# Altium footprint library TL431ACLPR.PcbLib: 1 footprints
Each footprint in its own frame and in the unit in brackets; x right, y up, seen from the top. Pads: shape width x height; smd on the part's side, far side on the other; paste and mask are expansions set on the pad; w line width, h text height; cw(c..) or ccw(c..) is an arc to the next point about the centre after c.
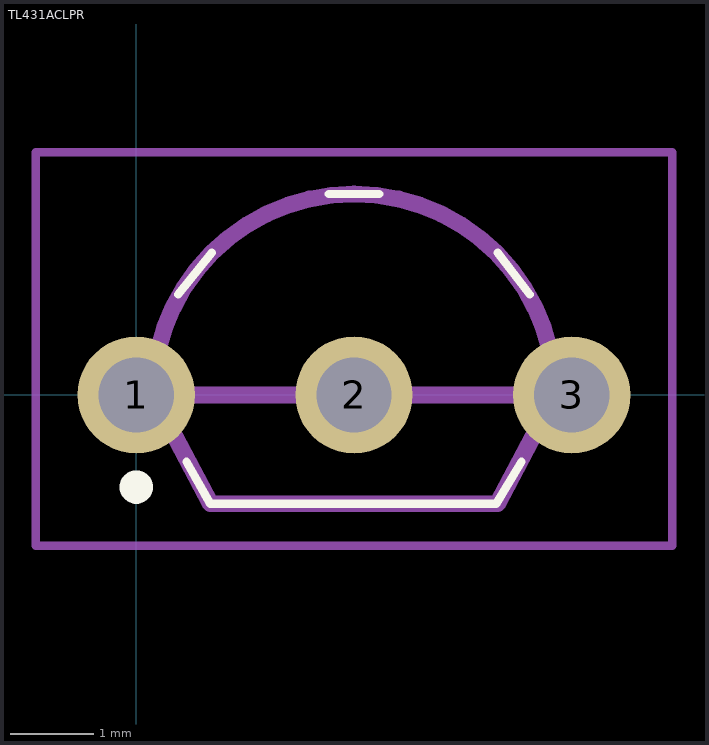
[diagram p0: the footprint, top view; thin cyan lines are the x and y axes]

## TL431ACLPR [mm]
pads (3):
  round 1.4 hole 0.9: 1(0,0) 2(2.6,0) 3(5.2,0)
Top Overlay:
  lines w0.1: 0.5,1.2 0.9,1.7 ; 0.6,-0.8 0.885,-1.3 4.3,-1.3 4.6,-0.8 ; 2.3,2.4 2.9,2.4 ; 4.315,1.7 4.7,1.2
  lines w0.2: -0.1,-1.1 -0.1,-1.1 ; -0.1,-1.1 ccw(c0,-1.1) 0.1,-1.1 ; -0.1,-1.1 cw(c0,-1.1) 0.1,-1.1 ; 0.1,-1.1 0.1,-1.1
Mechanical 15:
  lines w0.2: 0.2,0 5,0 ; 0.2,0 cw(c2.6,0) 5,0 ; 0.2,0 0.885,-1.3 4.315,-1.3 5,0 ; 5,0 5,0
Mechanical 20:
  lines w0.1: -1.2,-1.8 6.4,-1.8 ; -1.2,-1.8 -1.2,2.9 ; -1.2,-1.8 6.4,-1.8 ; -1.2,-1.8 -1.2,2.9 ; -1.2,2.9 6.4,2.9 ; -1.2,2.9 6.4,2.9 ; 6.4,-1.8 6.4,2.9 ; 6.4,-1.8 6.4,2.9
